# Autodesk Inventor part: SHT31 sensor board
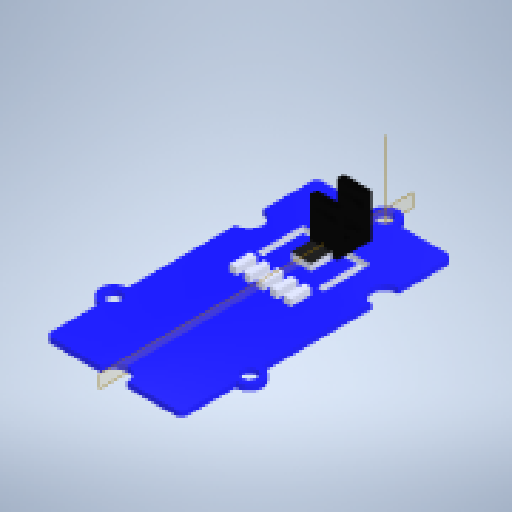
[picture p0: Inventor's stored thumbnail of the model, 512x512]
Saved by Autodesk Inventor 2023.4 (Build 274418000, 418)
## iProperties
Created: 2019-06
Part Number: SHT31 sensor board
Material: Générique
Document SubType Name: Modeling
Designer: mel
Density: 1 g/cm^3
Appearance: Par défaut
Sending System: SolidWorks 2018
Last Author: Hazel
Last Saved: 2019-07-03
Author: mel
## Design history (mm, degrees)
feature "SMDs"
node "Plan de construction1"
  node "Axe de construction1"
sketch "Esquisse1"
  geometry: L1 (0, 0.8)-(0, 8) reference; L2 (0, 9)-(6.47, 9); L3 (6.47, 4)-(0, 4); L4 (0, 4)-(0, 9); L5 (6.47, 8)-(2, 8); L6 (2, 8)-(2, 5); L7 (2, 5)-(6.47, 5); L8 (6.47, 9)-(6.47, 8); L9 (6.47, 5)-(6.47, 4); L10 (-0.8, 8)-(-0.8, 0.8) reference; 4 further points
  constraints: 16 end point, 4 parallel, 3 perpendicular, 2 horizontal, 1 collinear, 1 point on line
  dimensions: "d1" = 5 distance between parallel lines of L3 L2; "d2" = 3 distance between parallel lines of L7 L5; "d3" = 1 distance between parallel lines of L5 L2; "d4" = 1 distance between parallel lines of L3 L7 (derived); "d5" = 4 distance from line of point (0, 0) L3; "d6" = 7.27 distance between parallel lines of L10 L9; "d7" = 2.8 distance between parallel lines of L10 L6
extrude "Extrusion1" join sketch "Esquisse1" stored distance "d8" = 4; taper "d9" = 0 deg
node "Solide1"
other parameters: "d0" = 0
